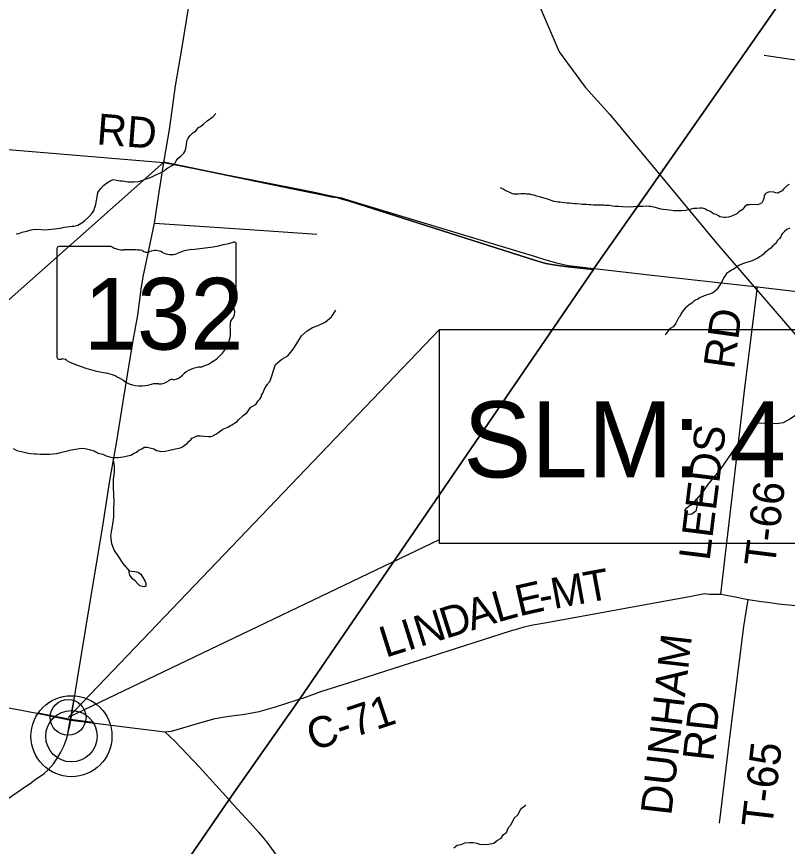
# Model space of a CAD drawing. Extents: x 0 to 39.3, y -3.9 to 22.
# Drawn here: x 4.682 to 6.099, y 15.566 to 17.092 of the extents above; entities that cross this region are included whole.
import ezdxf

# ---------------------------------------------------------------- set-up
doc = ezdxf.new("R2010")
doc.units = 0
for name, color, linetype in [('GM_X_Corporation', 7, 'Continuous'), ('GM_X_County_Road', 7, 'Continuous'), ('GM_X_County_Road_Text', 7, 'Continuous'), ('GM_X_Minor_Lake', 7, 'Continuous'), ('GM_X_Minor_River', 7, 'Continuous'), ('GM_X_Rail_Line', 7, 'Continuous'), ('GM_X_State_Location', 7, 'Continuous'), ('GM_X_State_Route', 7, 'Continuous'), ('GM_X_State_Shield', 7, 'Continuous'), ('GM_X_Township_Road', 7, 'Continuous'), ('GM_X_Township_Road_Text', 7, 'Continuous'), ('GM_X_Unincorporated', 7, 'Continuous'), ('GM_X_Unincorporated_Location', 7, 'Continuous'), ('SH_Text', 7, 'Continuous')]:
    doc.layers.add(name, color=color, linetype=linetype)

msp = doc.modelspace()

# ---------------------------------------------------------------- linework, layer by layer
at = {"layer": 'GM_X_Corporation'}
for points in [[(2.8431, 15.7483), (3.5402, 15.8703), (4.1293, 15.9727), (4.3975, 16.29), (4.5253, 16.4446), (4.9525, 16.8243), (5.1896, 16.7753), (5.2324, 16.7664), (5.2611, 16.7603), (5.2717, 16.7593), (5.2788, 16.7568), (5.2938, 16.7523), (5.6057, 16.653), (5.6339, 16.6439), (5.6444, 16.6406), (5.655, 16.638), (5.6693, 16.6354), (5.6908, 16.6325), (5.7298, 16.628), (5.7424, 16.6266), (5.744, 16.6289), (5.8398, 16.7652), (6.0256, 17.0319), (6.2667, 17.3782)], [(6.2667, 17.3782), (6.0256, 17.0319), (5.8398, 16.7652), (5.744, 16.6289), (5.7424, 16.6266), (5.2028, 15.8376), (5.0728, 15.652), (4.2376, 14.4362), (4.2334, 14.4302), (3.9536, 14.0228), (3.9474, 14.0138), (3.8692, 13.9), (7.894, 13.9)], [(4.2376, 14.4362), (5.0728, 15.652), (5.2028, 15.8376), (5.7424, 16.6266), (5.7298, 16.628), (5.6908, 16.6325), (5.6693, 16.6354), (5.655, 16.638), (5.6444, 16.6406), (5.6339, 16.6439), (5.6057, 16.653), (5.2938, 16.7523), (5.2788, 16.7568), (5.2717, 16.7593), (5.2611, 16.7603), (5.2324, 16.7664), (5.1896, 16.7753), (4.9525, 16.8243), (4.5253, 16.4446), (4.3975, 16.29), (4.1293, 15.9727), (3.5402, 15.8703), (2.8431, 15.7483)]]:
    msp.add_lwpolyline(points, dxfattribs=at)
at = {"layer": 'GM_X_County_Road'}
for points in [[(5.1963, 15.8349), (5.203, 15.8371), (5.208, 15.8387), (5.2431, 15.8512), (5.2922, 15.867), (5.5898, 15.9621), (5.6036, 15.9659), (5.6154, 15.9698), (5.631, 15.9732), (5.6531, 15.9768), (5.9222, 16.0263), (5.9374, 16.0293), (5.9462, 16.0313), (5.956, 16.0299), (5.9767, 16.0296), (5.9969, 16.0262), (6.0268, 16.0202)], [(6.0268, 16.0202), (6.0514, 16.0165), (6.0628, 16.015), (6.083, 16.0122), (6.1762, 16.0027), (6.2187, 16.0002), (6.2558, 15.9974), (6.3028, 15.9945), (6.4246, 15.9891), (6.4343, 15.9879), (6.4423, 15.9854), (6.4525, 15.9817), (6.4631, 15.976), (6.4731, 15.9697), (6.4828, 15.9637), (6.4896, 15.9614), (6.5024, 15.9597), (6.6105, 15.9526), (6.6296, 15.9515), (6.6393, 15.9517), (6.6484, 15.9529), (6.661, 15.956), (6.7203, 15.976)], [(4.9548, 15.7766), (4.9668, 15.7779), (5.0251, 15.7952), (5.0473, 15.8014), (5.0688, 15.8046), (5.0818, 15.8067), (5.0974, 15.8084), (5.1113, 15.8111), (5.1282, 15.8142), (5.1581, 15.8225), (5.1963, 15.8349)], [(4.782, 15.7981), (4.9548, 15.7766), (4.9731, 15.7597), (5.0182, 15.7115), (5.073, 15.6514), (5.0743, 15.65)], [(5.0743, 15.65), (5.0956, 15.6267), (5.1112, 15.6092), (5.1266, 15.5924), (5.1424, 15.574), (5.155, 15.556), (5.1754, 15.5265), (5.1921, 15.5009), (5.2098, 15.4786), (5.2345, 15.4441), (5.2536, 15.4152), (5.2661, 15.3873), (5.2927, 15.3374), (5.3304, 15.2615), (5.3393, 15.2452), (5.3481, 15.2331), (5.3602, 15.2247), (5.3705, 15.2168), (5.4035, 15.1935), (5.4231, 15.1777), (5.427, 15.1749)]]:
    msp.add_lwpolyline(points, dxfattribs=at)
at = {"layer": 'GM_X_Minor_Lake'}
for points in [[(4.8998, 16.0542), (4.896, 16.0576), (4.8931, 16.0604), (4.8902, 16.0648), (4.8891, 16.0698), (4.8892, 16.0729)], [(4.8892, 16.0729), (4.8994, 16.0716), (4.9058, 16.0703), (4.9103, 16.0668), (4.914, 16.0606), (4.9177, 16.0541), (4.9199, 16.0499), (4.9198, 16.0442), (4.916, 16.0435), (4.9088, 16.0448), (4.9047, 16.0486), (4.8998, 16.0541), (4.8998, 16.0542)]]:
    msp.add_lwpolyline(points, dxfattribs=at)
at = {"layer": 'GM_X_Minor_River'}
for points in [[(4.6813, 16.6921), (4.6859, 16.6932), (4.6924, 16.6953), (4.7004, 16.6971), (4.7069, 16.6989), (4.7119, 16.7), (4.7161, 16.7006), (4.7275, 16.7004), (4.7339, 16.6999), (4.74, 16.7002), (4.7461, 16.7009), (4.7518, 16.7012), (4.7572, 16.7018), (4.7617, 16.7025), (4.7652, 16.7032), (4.7697, 16.7043), (4.7751, 16.7049), (4.7797, 16.7056), (4.7835, 16.7063), (4.7873, 16.7066), (4.7903, 16.7073), (4.7945, 16.7084), (4.8022, 16.7124), (4.8076, 16.7169), (4.8149, 16.7233), (4.8208, 16.7304), (4.8247, 16.736), (4.8255, 16.7394), (4.8274, 16.7436), (4.8279, 16.747), (4.8291, 16.7534), (4.8304, 16.7603), (4.8317, 16.7682), (4.8344, 16.7724), (4.8367, 16.7757), (4.8421, 16.7814), (4.8475, 16.7855), (4.8556, 16.7906), (4.8602, 16.7921), (4.8655, 16.7912), (4.8693, 16.7904), (4.8727, 16.79), (4.8765, 16.7895), (4.8871, 16.7878), (4.8978, 16.7876), (4.9061, 16.7886), (4.913, 16.7904), (4.9187, 16.7926), (4.9245, 16.7944), (4.9318, 16.7977), (4.939, 16.8013), (4.9452, 16.8039), (4.9494, 16.8061), (4.9525, 16.8076), (4.9555, 16.8098), (4.9598, 16.8135), (4.9659, 16.8165), (4.969, 16.8187), (4.9728, 16.8217), (4.9756, 16.8266), (4.9791, 16.8315), (4.9841, 16.8348), (4.9895, 16.8404), (4.9911, 16.8438), (4.9923, 16.8472), (4.9935, 16.8514), (4.9943, 16.8571), (4.9948, 16.8612), (4.9956, 16.8646), (4.9976, 16.868), (5.0007, 16.8725), (5.0057, 16.8774), (5.0115, 16.8819), (5.0165, 16.8879), (5.0204, 16.8897), (5.0254, 16.8942), (5.0323, 16.8998), (5.0385, 16.9046), (5.0435, 16.9083), (5.0481, 16.9136)], [(6.1024, 16.7832), (6.099, 16.781), (6.092, 16.7743), (6.0893, 16.7713), (6.0847, 16.7687), (6.0816, 16.7672), (6.0778, 16.7677), (6.0745, 16.7692), (6.0665, 16.7694), (6.0623, 16.7683), (6.0584, 16.7657), (6.0565, 16.7616), (6.0556, 16.7574), (6.0544, 16.754), (6.0521, 16.7495), (6.0478, 16.7469), (6.0436, 16.7458), (6.0338, 16.746), (6.0292, 16.7457), (6.0254, 16.7454), (6.0212, 16.7428), (6.0188, 16.7398), (6.0157, 16.7364), (6.01, 16.7327), (6.0061, 16.729), (6.0004, 16.7264), (5.9954, 16.7242), (5.9908, 16.7228), (5.9855, 16.7221), (5.982, 16.7222), (5.9752, 16.7238), (5.9722, 16.7254), (5.9684, 16.7277), (5.9635, 16.7293), (5.9568, 16.734), (5.9511, 16.736), (5.9473, 16.7384), (5.9428, 16.7392), (5.9379, 16.7397), (5.9329, 16.739), (5.9264, 16.7388), (5.9222, 16.7377), (5.918, 16.7362), (5.9123, 16.7352), (5.9036, 16.7346), (5.8982, 16.7343), (5.8941, 16.7348), (5.8906, 16.7348), (5.8827, 16.7361), (5.8774, 16.7362), (5.8709, 16.7371), (5.8667, 16.7379), (5.8603, 16.7395), (5.8565, 16.7407), (5.8531, 16.7416), (5.8482, 16.7424), (5.8451, 16.7428), (5.841, 16.7429), (5.8334, 16.7427), (5.8254, 16.7424), (5.8162, 16.7418), (5.8121, 16.7415), (5.7961, 16.7418), (5.7893, 16.7423), (5.7824, 16.7424), (5.7779, 16.7433), (5.7718, 16.7441), (5.765, 16.7443), (5.7615, 16.7447), (5.7429, 16.745), (5.738, 16.7455), (5.7338, 16.7459), (5.7293, 16.746), (5.7217, 16.7465), (5.7186, 16.7466), (5.7114, 16.7475), (5.708, 16.7475), (5.7027, 16.748), (5.6977, 16.7485), (5.6943, 16.7489), (5.6886, 16.7494), (5.681, 16.7503), (5.678, 16.7503)], [(5.678, 16.7503), (5.6746, 16.7512), (5.6704, 16.752), (5.6651, 16.7536), (5.6617, 16.7548), (5.658, 16.756), (5.6538, 16.7572), (5.6474, 16.7593), (5.6432, 16.7601), (5.6379, 16.7617), (5.6337, 16.7633), (5.6296, 16.7641), (5.6258, 16.765), (5.6228, 16.7654), (5.6197, 16.7654), (5.6163, 16.7659), (5.6125, 16.7656), (5.6091, 16.7656), (5.6049, 16.7653), (5.5961, 16.7655), (5.5924, 16.7667), (5.5875, 16.7691), (5.5844, 16.7703), (5.5803, 16.7718), (5.5765, 16.7742), (5.572, 16.7769)], [(6.1037, 16.7025), (6.0984, 16.7003), (6.0942, 16.6974), (6.0899, 16.6929), (6.0876, 16.6899), (6.0868, 16.6869), (6.0848, 16.6838), (6.0798, 16.679), (6.079, 16.6756), (6.0759, 16.673), (6.0716, 16.6696), (6.0685, 16.6659), (6.0655, 16.6644), (6.0616, 16.6607), (6.0581, 16.6585), (6.055, 16.6547), (6.0516, 16.6521), (6.0481, 16.6499), (6.0446, 16.6473), (6.0408, 16.6458), (6.0366, 16.644), (6.0324, 16.6418), (6.0263, 16.6404), (6.0221, 16.6389), (6.0167, 16.6371), (6.0098, 16.6338), (6.0029, 16.629), (5.9956, 16.6246), (5.9906, 16.622), (5.9872, 16.6194), (5.9852, 16.616), (5.9825, 16.6119), (5.9813, 16.6088), (5.9774, 16.6021), (5.9734, 16.5957), (5.9707, 16.5919), (5.9684, 16.5885), (5.9638, 16.5848), (5.9607, 16.5833), (5.9557, 16.5815), (5.9527, 16.5808), (5.9496, 16.5793), (5.9462, 16.5783), (5.9423, 16.5764), (5.9389, 16.575), (5.9343, 16.5724), (5.9304, 16.5702), (5.9274, 16.5683), (5.9239, 16.5653), (5.9181, 16.5609), (5.915, 16.5586), (5.9116, 16.556), (5.9077, 16.5515), (5.905, 16.5478), (5.9034, 16.5448), (5.9011, 16.5406), (5.8987, 16.5376), (5.896, 16.5316), (5.894, 16.5278), (5.8913, 16.5244), (5.8889, 16.5211), (5.8851, 16.5188), (5.882, 16.5162), (5.8785, 16.5121), (5.8758, 16.5087), (5.8742, 16.5057)], [(5.1487, 16.4238), (5.1579, 16.4523), (5.1695, 16.462), (5.1806, 16.4678), (5.1907, 16.4802), (5.1974, 16.4907), (5.206, 16.505), (5.2164, 16.514), (5.226, 16.5203), (5.2367, 16.5239), (5.2494, 16.5298), (5.261, 16.5398), (5.2692, 16.5522)], [(5.0201, 16.321), (5.0265, 16.3201), (5.0349, 16.3196), (5.0399, 16.3199), (5.0429, 16.3209), (5.0483, 16.3239), (5.0522, 16.3265), (5.0614, 16.3332), (5.0706, 16.3368), (5.0806, 16.3431), (5.0845, 16.3454), (5.0876, 16.3472), (5.0903, 16.3502), (5.0988, 16.358), (5.1053, 16.3629), (5.1128, 16.3738), (5.1216, 16.3786), (5.1259, 16.3854), (5.1294, 16.3884), (5.1322, 16.3933), (5.1326, 16.3959), (5.1349, 16.3993), (5.1373, 16.4053), (5.1393, 16.4095), (5.1432, 16.4151), (5.1448, 16.4178), (5.1475, 16.4208), (5.1487, 16.4238)], [(6.1535, 16.4084), (6.149, 16.4012), (6.1423, 16.3895), (6.1349, 16.3783), (6.1268, 16.3685), (6.1141, 16.3585), (6.1037, 16.3515), (6.0914, 16.3448), (6.0789, 16.3428), (6.0679, 16.3437), (6.0474, 16.3441), (6.0352, 16.3413), (6.0221, 16.3274), (6.0135, 16.3143), (6.0042, 16.3015), (5.9944, 16.2868), (5.9847, 16.2726), (5.9745, 16.2572), (5.9633, 16.2441), (5.9525, 16.2306), (5.9439, 16.2178), (5.9327, 16.2051)], [(4.6755, 16.2976), (4.6823, 16.294), (4.6933, 16.2912), (4.7032, 16.2891), (4.7074, 16.2886), (4.715, 16.2877), (4.7188, 16.2877), (4.7252, 16.2872), (4.7363, 16.287), (4.7427, 16.2873), (4.7485, 16.2879), (4.7561, 16.2886), (4.763, 16.2903), (4.7675, 16.2914), (4.776, 16.2932), (4.7794, 16.2943), (4.7867, 16.296), (4.7939, 16.2971), (4.8, 16.2981), (4.8084, 16.2979), (4.8152, 16.2955), (4.8247, 16.2935), (4.8322, 16.2892), (4.8406, 16.2871), (4.8466, 16.284), (4.8515, 16.2827), (4.8549, 16.2815), (4.8595, 16.2811), (4.8686, 16.2809), (4.8736, 16.2816), (4.8808, 16.2826), (4.8858, 16.2841), (4.8919, 16.2855), (4.8984, 16.2888), (4.9023, 16.2906), (4.9069, 16.2947), (4.9123, 16.2969), (4.9165, 16.2999), (4.9219, 16.3002), (4.9268, 16.299), (4.9344, 16.2969), (4.9393, 16.2942), (4.9431, 16.2933), (4.9461, 16.2922), (4.9549, 16.2924), (4.9606, 16.2942), (4.969, 16.2959), (4.9743, 16.297), (4.9835, 16.2991), (4.987, 16.3006), (4.9924, 16.3047), (4.9955, 16.3069), (4.9993, 16.311), (5.0021, 16.3133), (5.0044, 16.3167), (5.009, 16.3185), (5.0136, 16.3211), (5.0201, 16.321)], [(4.8595, 16.2811), (4.8596, 16.2768), (4.8613, 16.265), (4.8612, 16.2543), (4.8598, 16.2414), (4.8599, 16.2251), (4.8605, 16.2137), (4.861, 16.1996), (4.8604, 16.1871), (4.8601, 16.1722), (4.8592, 16.162), (4.8567, 16.148), (4.855, 16.137), (4.8566, 16.1232), (4.8613, 16.1099), (4.8695, 16.0987), (4.8776, 16.086), (4.8892, 16.0729)], [(5.9327, 16.2051), (5.9324, 16.191), (5.9307, 16.1823), (5.9234, 16.1771), (5.9189, 16.176), (5.914, 16.1771), (5.9107, 16.1838), (5.9141, 16.1883)], [(5.9141, 16.1883), (5.9188, 16.192), (5.923, 16.1942), (5.9268, 16.1972), (5.9327, 16.2051)], [(5.4861, 15.5635), (5.4919, 15.568), (5.4991, 15.5693), (5.506, 15.5723), (5.5156, 15.5733), (5.5213, 15.5732), (5.5281, 15.5719), (5.533, 15.5703), (5.541, 15.5694), (5.5494, 15.5704), (5.5597, 15.5717), (5.5659, 15.5777), (5.5728, 15.581), (5.5775, 15.5878), (5.5825, 15.5915), (5.5865, 15.601), (5.5915, 15.6062), (5.5967, 15.6179), (5.6037, 15.6243), (5.6096, 15.6356), (5.6165, 15.6404), (5.6181, 15.6426)]]:
    msp.add_lwpolyline(points, dxfattribs=at)
at = {"layer": 'GM_X_Rail_Line'}
msp.add_lwpolyline([(4.1862, 18.6283), (4.1623, 18.5861), (4.1312, 18.5367), (4.1237, 18.4853), (4.1289, 18.4392), (4.1557, 18.406), (4.1976, 18.3765), (4.4754, 18.173), (4.9692, 17.8015), (5.0261, 17.7684), (5.2171, 17.6839), (5.3211, 17.6311), (5.3909, 17.5876), (5.4374, 17.541), (5.4654, 17.5053), (5.484, 17.4726), (5.6407, 17.117), (5.6795, 17.0269), (5.7276, 16.9617), (5.7726, 16.912), (5.9697, 16.6744), (6.1991, 16.4081)], dxfattribs=at)
at = {"layer": 'GM_X_State_Route'}
msp.add_line((4.7797, 15.7884), (4.782, 15.7981), dxfattribs=at)
for points in [[(4.9528, 16.8237), (4.964, 16.8881), (4.9743, 16.9642), (4.9863, 17.0356), (4.9981, 17.1073), (5.0097, 17.1775), (5.0147, 17.2084), (5.0198, 17.2398), (5.0263, 17.2907), (5.0289, 17.3087)], [(4.782, 15.7981), (4.7936, 15.8706), (4.8101, 15.9711), (4.8229, 16.0487), (4.84, 16.1513), (4.8535, 16.2389), (4.866, 16.3077), (4.8782, 16.3843), (4.8858, 16.4329), (4.8966, 16.4963), (4.9051, 16.5428), (4.9111, 16.5907), (4.9148, 16.6135), (4.9234, 16.6539), (4.9355, 16.712), (4.9443, 16.7691), (4.9528, 16.8237)], [(4.078, 15.9816), (4.1025, 15.9772), (4.1295, 15.9722), (4.1422, 15.9698), (4.1749, 15.9631), (4.1995, 15.9584), (4.2242, 15.9524), (4.255, 15.9439), (4.3031, 15.9285), (4.3521, 15.9144), (4.4117, 15.8968), (4.4634, 15.8805), (4.5074, 15.8675), (4.5537, 15.8532), (4.5983, 15.839), (4.6217, 15.8311), (4.6448, 15.8251), (4.6671, 15.821), (4.6909, 15.8167), (4.7344, 15.8079), (4.782, 15.7981)], [(4.7092, 15.6837), (4.7158, 15.6883), (4.733, 15.6999), (4.7403, 15.7071), (4.7498, 15.7179), (4.7563, 15.7273), (4.7632, 15.739), (4.7689, 15.7501), (4.7743, 15.7653), (4.7797, 15.7884)], [(4.2743, 15.4296), (4.2833, 15.4311), (4.3054, 15.4346), (4.3352, 15.4421), (4.3653, 15.4504), (4.3932, 15.4595), (4.4122, 15.4682), (4.4234, 15.4738), (4.435, 15.481), (4.4487, 15.4895), (4.4623, 15.4992), (4.4766, 15.5093), (4.4931, 15.5243), (4.5057, 15.5343), (4.5214, 15.548), (4.5359, 15.5594), (4.553, 15.5731), (4.5764, 15.5926), (4.6098, 15.6159), (4.6349, 15.6332), (4.6665, 15.6543), (4.6902, 15.6706), (4.7092, 15.6837)]]:
    msp.add_lwpolyline(points, dxfattribs=at)
at = {"layer": 'GM_X_State_Shield'}
for p, q in [((4.7563, 16.6655), (4.7563, 16.4654)), ((4.8561, 16.6689), (4.7596, 16.6689)), ((5.0859, 16.5692), (5.0859, 16.6739)), ((5.0859, 16.5692), (5.0859, 16.5692))]:
    msp.add_line(p, q, dxfattribs=at)
for centre, major_axis, start_param, end_param in [((4.9685, 16.9418), (0.3495, 0), 4.814394, 5.042369), ((5.0823, 16.6743), (0.00367, 0), 6.141152, 7.989035), ((4.7601, 16.6659), (0.00382, 0), 1.712693, 3.28349), ((4.8791, 16.6922), (0.037, 0), 4.042523, 4.731795), ((4.8914, 16.5566), (0.133, 0), 1.404758, 1.657858), ((4.9215, 16.6669), (0.0107, 0), 3.836095, 5.185415), ((4.9372, 16.6438), (0.0222, 0), 0.950623, 2.079405), ((5.0131, 16.6078), (0.0703, 0), 1.699011, 2.107814), ((4.9659, 16.6755), (0.0267, 0), 4.081561, 5.145723), ((5.082, 16.5688), (0.00393, 0), 5.05454, 6.418171), ((5.0851, 16.5615), (0.00568, 0), 1.883978, 3.671073), ((5.0489, 16.5483), (0.0341, 0), 5.934695, 6.695948), ((5.0991, 16.5254), (0.0248, 0), 2.387724, 3.262537), ((4.9881, 16.5121), (0.0874, 0), 5.101752, 6.440018), ((4.7601, 16.4649), (0.00385, 0), 3.00124, 4.508301), ((4.7607, 16.4854), (0.0294, 0), 4.665946, 4.897461), ((4.7667, 16.4538), (0.0106, 0), 0.519207, 1.627899), ((4.9006, 16.6336), (0.2524, 0), 4.195997, 4.488961), ((5.025, 16.4092), (0.0479, 0), 1.647645, 2.488434), ((4.8253, 16.3755), (0.079, 0), 0.823519, 1.323587), ((4.9643, 16.446), (0.0282, 0), 4.937069, 5.64225), ((4.9107, 16.4528), (0.0501, 0), 4.026481, 4.996735), ((4.9397, 16.3836), (0.0412, 0), 1.495662, 1.94098), ((4.9433, 16.4378), (0.0267, 0), 4.691044, 5.507374), ((4.9675, 16.4185), (0.00752, 0), 1.147584, 2.315152)]:
    msp.add_ellipse(centre, major_axis=major_axis, ratio=0.8, start_param=start_param, end_param=end_param, dxfattribs=at)
at = {"layer": 'GM_X_Township_Road'}
for p, q in [((6.0562, 17.021), (6.2251, 16.9948)), ((4.9355, 16.712), (5.1104, 16.7001)), ((5.1104, 16.7001), (5.2339, 16.6916))]:
    msp.add_line(p, q, dxfattribs=at)
for points in [[(4.5123, 16.8602), (4.9528, 16.8237)], [(4.9528, 16.8237), (5.19, 16.7769), (5.233, 16.7681), (5.2541, 16.7635), (5.2664, 16.7612), (5.2795, 16.7586), (5.2944, 16.7538), (5.6071, 16.6594), (5.6362, 16.6506), (5.6505, 16.646), (5.6619, 16.6426), (5.6724, 16.6395), (5.6964, 16.634), (5.7286, 16.6301), (5.7323, 16.6297)], [(5.7323, 16.6297), (5.7442, 16.6283), (5.8452, 16.6172), (6.0439, 16.5946), (6.1845, 16.5782)], [(5.9767, 16.0296), (6.0094, 16.3079), (6.0217, 16.4139), (6.0439, 16.5946)], [(5.9746, 15.609), (5.9947, 15.7759), (6.0191, 15.9705), (6.0268, 16.0202)]]:
    msp.add_lwpolyline(points, dxfattribs=at)
at = {"layer": 'GM_X_Unincorporated'}
for radius in [0.0744, 0.0472]:
    msp.add_circle((4.7829, 15.7686), radius, dxfattribs=at)
at = {"layer": 'GM_X_Unincorporated_Location'}
msp.add_line((4.7829, 15.7686), (4.7829, 15.7686), dxfattribs=at)
at = {"layer": 'SH_Text'}
for p, q in [((4.7768, 15.8033), (5.4598, 16.5161)), ((4.7772, 15.8038), (5.4598, 16.1303))]:
    msp.add_line(p, q, dxfattribs=at)
msp.add_lwpolyline([(5.4598, 16.5161), (6.8805, 16.5161), (6.8805, 16.1228), (5.4598, 16.1228)], close=True, dxfattribs=at)
for points in [[(4.7887, 15.8442), (4.7744, 15.7667), (4.7744, 15.7667)], [(4.7216, 15.8119), (4.7805, 15.7997), (4.8235, 15.7944)]]:
    msp.add_lwpolyline(points, dxfattribs=at)
msp.add_circle((4.7768, 15.8033), 0.0329, dxfattribs=at)

# ---------------------------------------------------------------- texts
at = {"layer": 'GM_X_County_Road_Text'}
for s, height, rotation, p in [('M', 0.0568, 10.4291, (5.6697, 16.0024)), ('T', 0.0568, 10.4241, (5.7304, 16.0136)), ('E', 0.0568, 12.767, (5.6059, 15.9888)), ('L', 0.0568, 15.8795, (5.5659, 15.9774)), ('A', 0.0568, 17.4592, (5.5186, 15.9625)), ('-', 0.0568, 10.6738, (5.6469, 15.9981)), ('D', 0.0568, 17.4951, (5.4709, 15.9475)), ('N', 0.0568, 17.4951, (5.4232, 15.9325)), ('I', 0.0568, 17.4952, (5.4009, 15.9255)), ('L', 0.0568, 17.4944, (5.3604, 15.9127)), ('C-71', 0.05682, 18.4355, (5.227, 15.7411))]:
    msp.add_text(s, height=height, rotation=rotation, dxfattribs=at).set_placement(p)
at = {"layer": 'GM_X_State_Location'}
msp.add_text('132', height=0.000189, rotation=0, dxfattribs=at).set_placement((4.8506, 16.5383))
for s in ['s', 'r']:
    msp.add_text(s, height=0.000189, dxfattribs=at).set_placement((4.9174, 16.5521))
at = {"layer": 'GM_X_State_Shield'}
msp.add_text('132', height=0.13184, dxfattribs=at).set_placement((4.8053, 16.4795))
at = {"layer": 'GM_X_Township_Road_Text'}
for s, rotation, p in [('RD', 355.563, (4.8281, 16.857)), ('RD', 82.0798, (6.0009, 16.442)), ('LEEDS', 82.9029, (5.9559, 16.09)), ('T-66', 82.8748, (6.0759, 16.0783)), ('DUNHAM', 83.4065, (5.8856, 15.6216)), ('RD', 83.5502, (5.9628, 15.721)), ('T-65', 83.2691, (6.071, 15.599))]:
    msp.add_text(s, height=0.05682, rotation=rotation, dxfattribs=at).set_placement(p)
at = {"layer": 'SH_Text'}
msp.add_text('SLM: 4.97-4.99', height=0.14, dxfattribs=at).set_placement((5.5033, 16.2444))

doc.saveas('drawing.dxf')
